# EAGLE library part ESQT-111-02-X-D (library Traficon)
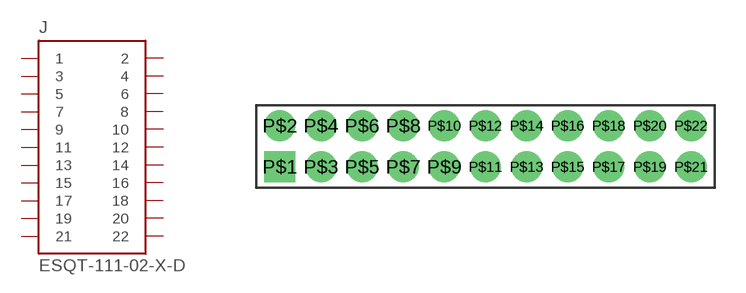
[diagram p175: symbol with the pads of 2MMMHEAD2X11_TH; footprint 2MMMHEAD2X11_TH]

Designator prefix J

## ESQT-111-02-X-D  [2MMMHEAD2X11_TH]
P$1  1  pas
P$2  2  pas
P$3  3  pas
P$4  4  pas
P$5  5  pas
P$6  6  pas
P$7  7  pas
P$8  8  pas
P$9  9  pas
P$10  10  pas
P$11  11  pas
P$12  12  pas
P$13  13  pas
P$14  14  pas
P$15  15  pas
P$16  16  pas
P$17  17
P$18  18
P$19  19
P$20  20
P$21  21
P$22  22

## Footprint 2MMMHEAD2X11_TH (pad centres in mm)
drill 1 square: P$1 -10,-1
drill 1 round: P$2 -10,1; P$3 -8,-1; P$4 -8,1; P$5 -6,-1; P$6 -6,1; P$7 -4,-1; P$8 -4,1; P$9 -2,-1; P$10 -2,1; P$11 0,-1; P$12 0,1; P$13 2,-1; P$14 2,1; P$15 4,-1; P$16 4,1; P$17 6,-1; P$18 6,1; P$19 8,-1; P$20 8,1; P$21 10,-1; P$22 10,1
